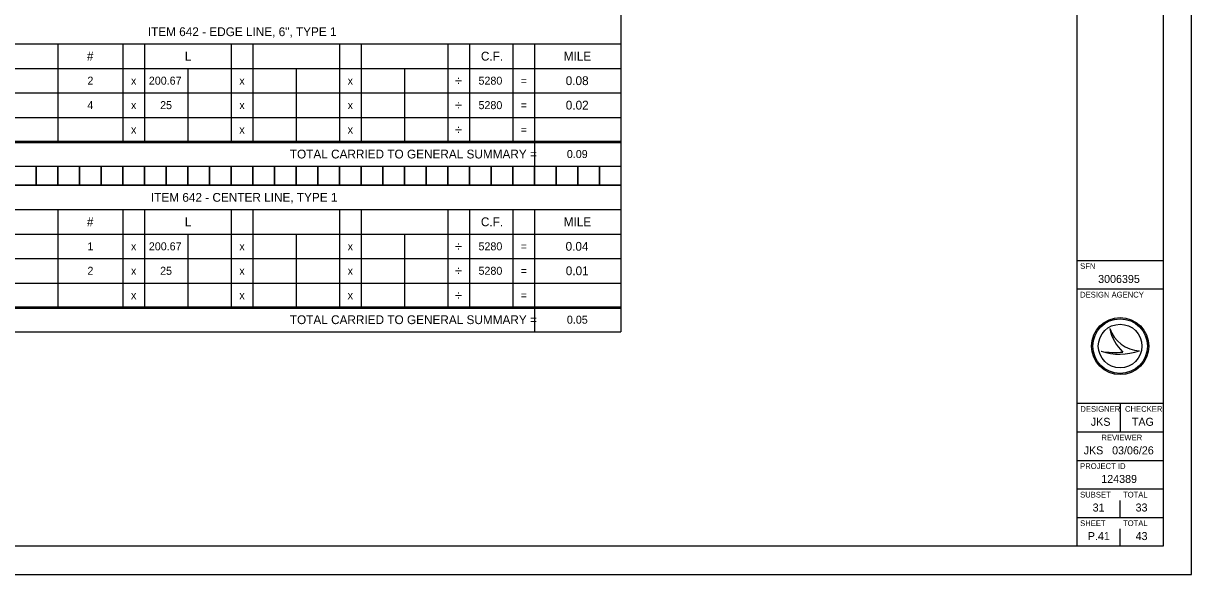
# Model space of a CAD drawing. Extents: x 0 to 34, y 0 to 22.
# Drawn here: x 13.57 to 34, y 0 to 9.65 of the extents above; entities that cross this region are included whole.
import ezdxf

# ---------------------------------------------------------------- set-up
doc = ezdxf.new("R2010")
doc.units = 0
for name, color, linetype in [('Default', 7, 'Continuous'), ('SH_Border', 7, 'Continuous'), ('SH_Cut_Line', 7, 'Continuous'), ('SH_Data', 7, 'Continuous')]:
    doc.layers.add(name, color=color, linetype=linetype)

msp = doc.modelspace()

# ---------------------------------------------------------------- linework, layer by layer
at = {"layer": 'Default'}
for p, q in [((24.021, 10.485), (24.021, 7.564)), ((10.763, 9.288), (24.021, 9.288)), ((14.172, 9.288), (14.172, 7.586)), ((15.308, 9.288), (15.308, 7.586)), ((15.687, 9.288), (15.687, 7.586)), ((17.203, 9.288), (17.203, 7.586)), ((17.581, 9.288), (17.581, 7.586)), ((19.097, 9.288), (19.097, 7.586)), ((19.476, 9.288), (19.476, 7.586)), ((20.991, 9.288), (20.991, 7.586)), ((21.37, 9.288), (21.37, 7.586)), ((22.127, 9.288), (22.127, 7.586)), ((22.506, 9.288), (22.506, 7.586)), ((10.763, 8.859), (24.021, 8.859)), ((16.445, 8.859), (16.445, 7.586)), ((18.339, 8.859), (18.339, 7.586)), ((20.233, 8.859), (20.233, 7.586)), ((10.763, 8.431), (24.021, 8.431)), ((10.763, 8.003), (24.021, 8.003)), ((10.763, 7.586), (24.021, 7.586)), ((10.763, 7.564), (24.021, 7.564)), ((22.506, 7.564), (22.506, 7.147)), ((24.021, 7.586), (24.021, 4.665)), ((10.763, 7.147), (24.021, 7.147)), ((10.763, 6.817), (24.021, 6.817)), ((10.763, 6.389), (24.021, 6.389)), ((14.172, 6.389), (14.172, 4.687)), ((15.308, 6.389), (15.308, 4.687)), ((15.687, 6.389), (15.687, 4.687)), ((17.203, 6.389), (17.203, 4.687)), ((17.581, 6.389), (17.581, 4.687)), ((19.097, 6.389), (19.097, 4.687)), ((19.476, 6.389), (19.476, 4.687)), ((20.991, 6.389), (20.991, 4.687)), ((21.37, 6.389), (21.37, 4.687)), ((22.127, 6.389), (22.127, 4.687)), ((22.506, 6.389), (22.506, 4.687)), ((10.763, 5.961), (24.021, 5.961)), ((16.445, 5.961), (16.445, 4.687)), ((18.339, 5.961), (18.339, 4.687)), ((20.233, 5.961), (20.233, 4.687)), ((10.763, 5.532), (24.021, 5.532)), ((10.763, 5.104), (24.021, 5.104)), ((10.763, 4.687), (24.021, 4.687)), ((10.763, 4.665), (24.021, 4.665)), ((22.506, 4.665), (22.506, 4.248)), ((24.021, 4.687), (24.021, 4.248)), ((10.763, 4.248), (24.021, 4.248))]:
    msp.add_line(p, q, dxfattribs=at)
for points in [[(13.414, 7.147), (13.793, 7.147), (13.793, 6.817), (13.414, 6.817)], [(13.793, 7.147), (14.172, 7.147), (14.172, 6.817), (13.793, 6.817)], [(14.172, 7.147), (14.551, 7.147), (14.551, 6.817), (14.172, 6.817)], [(14.551, 7.147), (14.93, 7.147), (14.93, 6.817), (14.551, 6.817)], [(14.93, 7.147), (15.308, 7.147), (15.308, 6.817), (14.93, 6.817)], [(15.308, 7.147), (15.687, 7.147), (15.687, 6.817), (15.308, 6.817)], [(15.687, 7.147), (16.066, 7.147), (16.066, 6.817), (15.687, 6.817)], [(16.066, 7.147), (16.445, 7.147), (16.445, 6.817), (16.066, 6.817)], [(16.445, 7.147), (16.824, 7.147), (16.824, 6.817), (16.445, 6.817)], [(16.824, 7.147), (17.203, 7.147), (17.203, 6.817), (16.824, 6.817)], [(17.203, 7.147), (17.581, 7.147), (17.581, 6.817), (17.203, 6.817)], [(17.581, 7.147), (17.96, 7.147), (17.96, 6.817), (17.581, 6.817)], [(17.96, 7.147), (18.339, 7.147), (18.339, 6.817), (17.96, 6.817)], [(18.339, 7.147), (18.718, 7.147), (18.718, 6.817), (18.339, 6.817)], [(18.718, 7.147), (19.097, 7.147), (19.097, 6.817), (18.718, 6.817)], [(19.097, 7.147), (19.476, 7.147), (19.476, 6.817), (19.097, 6.817)], [(19.476, 7.147), (19.854, 7.147), (19.854, 6.817), (19.476, 6.817)], [(19.854, 7.147), (20.233, 7.147), (20.233, 6.817), (19.854, 6.817)], [(20.233, 7.147), (20.612, 7.147), (20.612, 6.817), (20.233, 6.817)], [(20.612, 7.147), (20.991, 7.147), (20.991, 6.817), (20.612, 6.817)], [(20.991, 7.147), (21.37, 7.147), (21.37, 6.817), (20.991, 6.817)], [(21.37, 7.147), (21.748, 7.147), (21.748, 6.817), (21.37, 6.817)], [(21.748, 7.147), (22.127, 7.147), (22.127, 6.817), (21.748, 6.817)], [(22.127, 7.147), (22.506, 7.147), (22.506, 6.817), (22.127, 6.817)], [(22.506, 7.147), (22.885, 7.147), (22.885, 6.817), (22.506, 6.817)], [(22.885, 7.147), (23.264, 7.147), (23.264, 6.817), (22.885, 6.817)], [(23.264, 7.147), (23.643, 7.147), (23.643, 6.817), (23.264, 6.817)], [(23.643, 7.147), (24.021, 7.147), (24.021, 6.817), (23.643, 6.817)]]:
    msp.add_lwpolyline(points, close=True, dxfattribs=at)
at = {"layer": 'SH_Border'}
for p, q in [((32, 0.5), (32, 21.5)), ((32, 5.5), (33.5, 5.5)), ((32, 5), (33.5, 5)), ((32, 3), (33.5, 3)), ((32.75, 3), (32.75, 2.5)), ((32, 2.5), (33.5, 2.5)), ((32, 2), (33.5, 2)), ((32, 1.5), (33.5, 1.5)), ((32, 1), (33.5, 1))]:
    msp.add_line(p, q, dxfattribs=at)
msp.add_lwpolyline([(1.5, 21.5), (33.5, 21.5), (33.5, 0.5), (1.5, 0.5)], close=True, dxfattribs=at)
at = {"layer": 'SH_Cut_Line'}
msp.add_lwpolyline([(0, 0), (34, 0), (34, 22), (0, 22)], close=True, dxfattribs=at)
at = {"layer": 'SH_Data'}
for p, q in [((32.567, 4.31), (32.567, 4.31)), ((32.417, 3.91), (32.417, 3.91)), ((32.75, 4), (32.75, 4)), ((33.087, 3.919), (33.087, 3.919)), ((32.75, 1), (32.75, 1.3)), ((32.375, 0.675), (32.375, 0.675)), ((32.75, 0.5), (32.75, 0.8))]:
    msp.add_line(p, q, dxfattribs=at)
for radius in [0.5, 0.477, 0.477, 0.382]:
    msp.add_circle((32.75, 4), radius, dxfattribs=at)
for centre, radius, start, end in [((33.116, 4.498), 0.58, 198.9257, 198.9319), ((33.347, 4.47), 0.796, 191.6379, 191.6421), ((33.116, 4.498), 0.58, 198.9319, 267.1657), ((33.347, 4.47), 0.796, 191.6421, 226.0947), ((32.739, 4.87), 1.013, 251.4576, 290.0832), ((32.648, 5.154), 1.266, 259.4964, 259.4995), ((32.739, 4.87), 1.013, 251.4527, 251.4576), ((32.648, 5.154), 1.266, 259.4995, 276.6672)]:
    msp.add_arc(centre, radius, start, end, dxfattribs=at)

# ---------------------------------------------------------------- texts
at = {"layer": 'Default'}
for s, height, p in [('ITEM 642 - EDGE LINE, 6", TYPE 1', 0.154, (15.746, 9.425)), ('#', 0.154, (14.682, 8.997)), ('L', 0.154, (16.394, 8.997)), ('C.F.', 0.154, (21.571, 8.997)), ('MILE', 0.154, (23.02, 8.997)), ('2', 0.14, (14.69, 8.575)), ('x', 0.14, (15.452, 8.575)), ('200.67', 0.14, (15.764, 8.575)), ('x', 0.14, (17.347, 8.575)), ('x', 0.14, (19.241, 8.575)), ('÷', 0.168, (21.118, 8.561)), ('5280', 0.14, (21.529, 8.575)), ('=', 0.14, (22.267, 8.575)), ('0.08', 0.154, (23.054, 8.568)), ('4', 0.14, (14.688, 8.147)), ('x', 0.14, (15.452, 8.147)), ('25', 0.14, (15.961, 8.147)), ('x', 0.14, (17.347, 8.147)), ('x', 0.14, (19.241, 8.147)), ('÷', 0.168, (21.118, 8.133)), ('5280', 0.14, (21.529, 8.147)), ('=', 0.14, (22.267, 8.147)), ('0.02', 0.154, (23.055, 8.14)), ('x', 0.14, (15.452, 7.719)), ('x', 0.14, (17.347, 7.719)), ('x', 0.14, (19.241, 7.719)), ('÷', 0.168, (21.118, 7.705)), ('=', 0.14, (22.267, 7.719)), ('TOTAL CARRIED TO GENERAL SUMMARY =', 0.154, (18.23, 7.284)), ('0.09', 0.14, (23.074, 7.291)), ('ITEM 642 - CENTER LINE, TYPE 1', 0.154, (15.801, 6.526)), ('#', 0.154, (14.682, 6.098)), ('L', 0.154, (16.394, 6.098)), ('C.F.', 0.154, (21.571, 6.098)), ('MILE', 0.154, (23.02, 6.098)), ('1', 0.14, (14.69, 5.676)), ('x', 0.14, (15.452, 5.676)), ('200.67', 0.14, (15.764, 5.676)), ('x', 0.14, (17.347, 5.676)), ('x', 0.14, (19.241, 5.676)), ('÷', 0.168, (21.118, 5.662)), ('5280', 0.14, (21.529, 5.676)), ('=', 0.14, (22.267, 5.676)), ('0.04', 0.154, (23.052, 5.669)), ('2', 0.14, (14.69, 5.248)), ('x', 0.14, (15.452, 5.248)), ('25', 0.14, (15.961, 5.248)), ('x', 0.14, (17.347, 5.248)), ('x', 0.14, (19.241, 5.248)), ('÷', 0.168, (21.118, 5.234)), ('5280', 0.14, (21.529, 5.248)), ('=', 0.14, (22.267, 5.248)), ('0.01', 0.154, (23.055, 5.241)), ('x', 0.14, (15.452, 4.82)), ('x', 0.14, (17.347, 4.82)), ('x', 0.14, (19.241, 4.82)), ('÷', 0.168, (21.118, 4.806)), ('=', 0.14, (22.267, 4.82)), ('TOTAL CARRIED TO GENERAL SUMMARY =', 0.154, (18.23, 4.385)), ('0.05', 0.14, (23.075, 4.392))]:
    msp.add_text(s, height=height, dxfattribs=at).set_placement(p)
at = {"layer": 'SH_Data'}
for s, height, p in [('SFN', 0.1, (32.05, 5.35)), ('3006395', 0.14, (32.365, 5.105)), ('DESIGN AGENCY', 0.1, (32.05, 4.85)), ('DESIGNER', 0.1, (32.054, 2.85)), ('CHECKER', 0.1, (32.835, 2.85)), ('JKS', 0.14, (32.237, 2.605)), ('TAG', 0.14, (32.955, 2.605)), ('REVIEWER', 0.1, (32.422, 2.35)), ('03/06/26', 0.14, (32.609, 2.105)), ('JKS', 0.14, (32.112, 2.105)), ('PROJECT ID', 0.1, (32.05, 1.85)), ('124389', 0.14, (32.42, 1.605)), ('SUBSET', 0.1, (32.05, 1.35)), ('TOTAL', 0.1, (32.8, 1.35)), ('31', 0.14, (32.269, 1.105)), ('33', 0.14, (33.02, 1.105)), ('SHEET', 0.1, (32.05, 0.85)), ('TOTAL', 0.1, (32.8, 0.85)), ('P.41', 0.14, (32.184, 0.605)), ('43', 0.14, (33.02, 0.605))]:
    msp.add_text(s, height=height, dxfattribs=at).set_placement(p)

doc.saveas('drawing.dxf')
